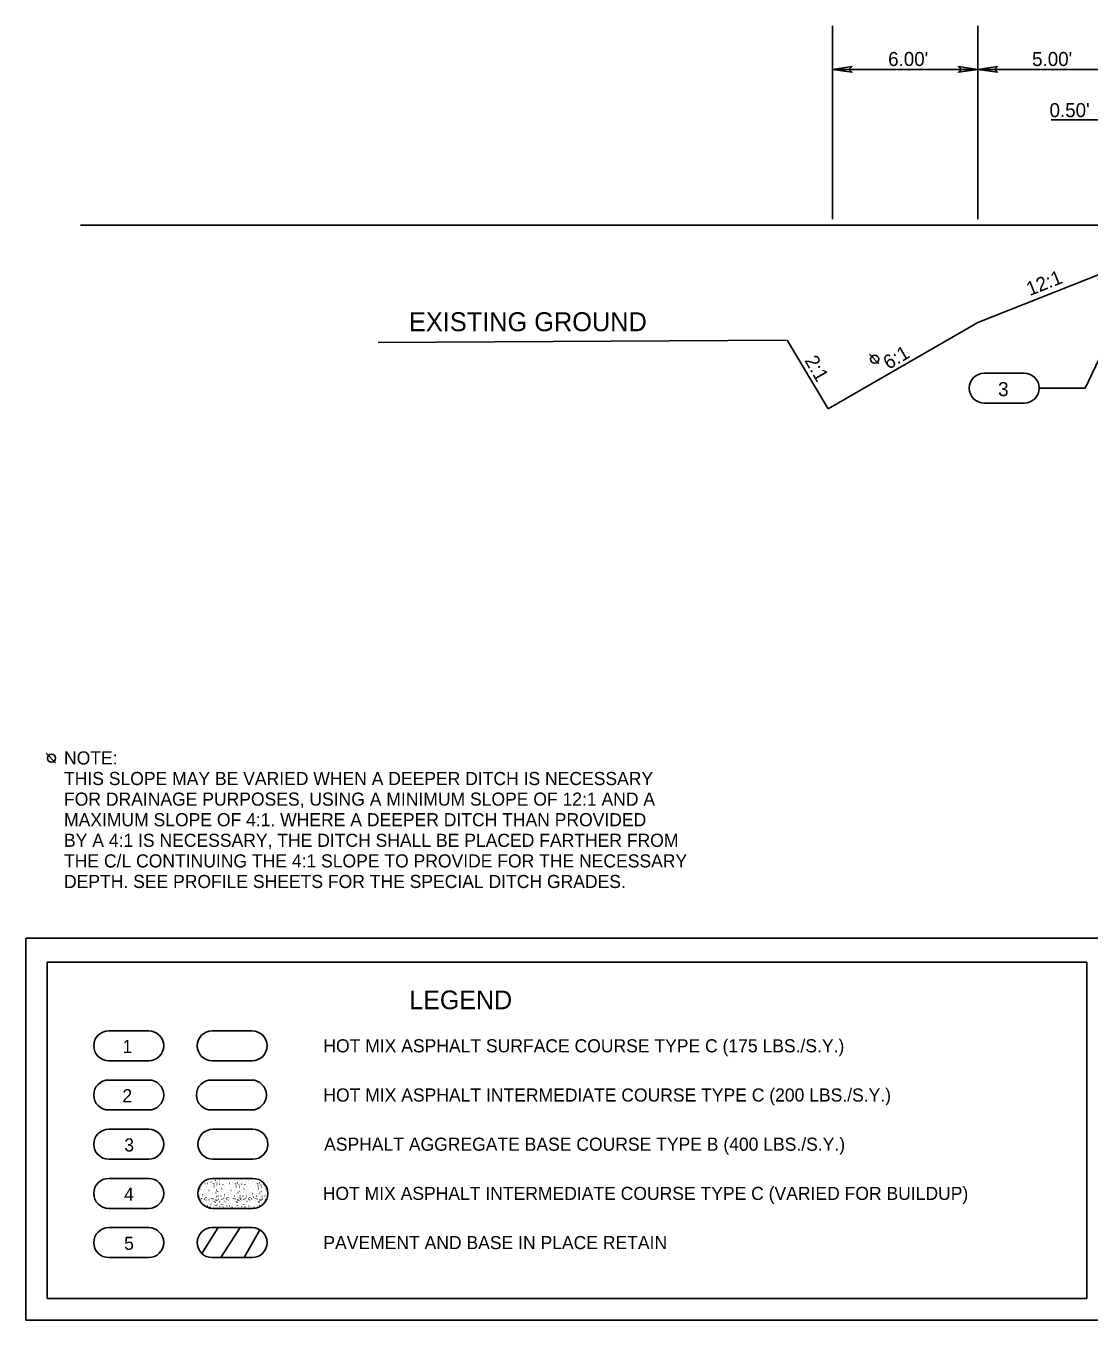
# Model space of a CAD drawing. Extents: x -8855 to -7217, y 44218 to 45252.
# Drawn here: x -8855 to -8287, y 44224 to 44916 of the extents above; entities that cross this region are included whole.
import ezdxf

# ---------------------------------------------------------------- set-up
doc = ezdxf.new("R2010")
doc.units = 0
for name, color, linetype in [('Default', 7, 'Continuous'), ('RD_EX_Misc', 7, 'Continuous'), ('RD_XS_Greenside', 7, 'Continuous'), ('RD_XS_Pave', 7, 'Continuous')]:
    doc.layers.add(name, color=color, linetype=linetype)

msp = doc.modelspace()

# ---------------------------------------------------------------- linework, layer by layer
at = {"layer": 'Default'}
for p, q in [((-8825.74, 44809.35), (-8001.4, 44809.35)), ((-8666.76, 44746.54), (-8448.82, 44747.86)), ((-8399.37, 44735.23), (-8404.39, 44740.39)), ((-8839.14, 44522.13), (-8844.16, 44527.29))]:
    msp.add_line(p, q, dxfattribs=at)
for points in [[(-8424.14, 44892.47), (-8413.75, 44893.97), (-8415.35, 44892.47), (-8413.75, 44890.98)], [(-8346.4, 44892.47), (-8356.79, 44890.98), (-8355.19, 44892.47), (-8356.79, 44893.97)], [(-8346.4, 44892.47), (-8336.01, 44893.97), (-8337.61, 44892.47), (-8336.01, 44890.98)]]:
    msp.add_lwpolyline(points, close=True, dxfattribs=at)
for centre in [(-8401.53, 44737.68), (-8841.3, 44524.59)]:
    msp.add_circle(centre, 2.17, dxfattribs=at)
at = {"layer": 'RD_EX_Misc'}
for p, q in [((-8424.14, 44812.42), (-8424.14, 44915.75)), ((-8346.4, 44812.42), (-8346.4, 44915.75)), ((-8346.4, 44892.47), (-8424.14, 44892.47)), ((-8346.4, 44892.47), (-8266.4, 44892.47)), ((-8307.35, 44865.58), (-8276.4, 44865.58)), ((-8289.09, 44722.23), (-8274.04, 44753.93)), ((-8321.67, 44730.23), (-8343.03, 44730.23)), ((-8313.67, 44722.23), (-8289.09, 44722.23)), ((-8343.03, 44714.23), (-8321.67, 44714.23)), ((-8810.73, 44378.93), (-8789.37, 44378.93)), ((-8734.11, 44378.93), (-8755.47, 44378.93)), ((-8789.37, 44362.93), (-8810.73, 44362.93)), ((-8755.47, 44362.93), (-8734.11, 44362.93)), ((-8810.73, 44352.65), (-8789.37, 44352.65)), ((-8789.37, 44336.65), (-8810.73, 44336.65)), ((-8810.73, 44326.37), (-8789.37, 44326.37)), ((-8755.07, 44326.37), (-8733.71, 44326.37)), ((-8755.07, 44326.37), (-8733.71, 44326.37)), ((-8789.37, 44310.37), (-8810.73, 44310.37)), ((-8733.71, 44310.37), (-8755.07, 44310.37)), ((-8733.71, 44310.37), (-8755.07, 44310.37)), ((-8810.73, 44300.09), (-8789.37, 44300.09)), ((-8761.66, 44296.07), (-8761.72, 44296.05)), ((-8761.42, 44296.74), (-8761.4, 44296.8)), ((-8760.61, 44295.64), (-8760.65, 44295.67)), ((-8759.3, 44297.31), (-8759.28, 44297.38)), ((-8758.29, 44299.27), (-8758.36, 44299.26)), ((-8758.28, 44295.94), (-8758.31, 44295.97)), ((-8757.84, 44297.37), (-8757.91, 44297.35)), ((-8757.4, 44298.63), (-8757.44, 44298.66)), ((-8756.69, 44294.89), (-8756.67, 44294.96)), ((-8756.54, 44296.77), (-8756.52, 44296.83)), ((-8756.08, 44298.15), (-8756.15, 44298.14)), ((-8755.66, 44299.31), (-8755.64, 44299.37)), ((-8755.6, 44295.58), (-8755.66, 44295.57)), ((-8754.79, 44297.4), (-8754.76, 44297.47)), ((-8754.49, 44296.57), (-8754.53, 44296.61)), ((-8754.39, 44295.5), (-8754.37, 44295.56)), ((-8754.27, 44299.64), (-8754.25, 44299.7)), ((-8753.75, 44299.12), (-8753.82, 44299.11)), ((-8753.69, 44297.7), (-8753.76, 44297.68)), ((-8753.72, 44296.23), (-8753.7, 44296.3)), ((-8752.92, 44296.57), (-8752.95, 44296.6)), ((-8752.9, 44297.73), (-8752.87, 44297.8)), ((-8752.63, 44295.46), (-8752.69, 44295.43)), ((-8752.57, 44298.72), (-8752.61, 44298.75)), ((-8751.65, 44299.49), (-8751.63, 44299.55)), ((-8751.42, 44296.97), (-8751.46, 44297)), ((-8751.39, 44298.54), (-8751.43, 44298.57)), ((-8751.15, 44295.73), (-8751.18, 44295.76)), ((-8750.47, 44298.22), (-8750.45, 44298.28)), ((-8749.92, 44296.07), (-8749.99, 44296.05)), ((-8749.69, 44296.74), (-8749.66, 44296.8)), ((-8749.23, 44300.03), (-8749.21, 44300.09)), ((-8749.18, 44297.87), (-8749.21, 44297.9)), ((-8748.88, 44295.64), (-8748.91, 44295.67)), ((-8748.58, 44299.78), (-8748.61, 44299.81)), ((-8747.76, 44298.78), (-8747.79, 44298.81)), ((-8747.57, 44297.31), (-8747.54, 44297.38)), ((-8746.56, 44299.27), (-8746.63, 44299.26)), ((-8746.55, 44295.94), (-8746.58, 44295.97)), ((-8746.11, 44297.37), (-8746.17, 44297.35)), ((-8745.67, 44298.63), (-8745.7, 44298.66)), ((-8744.96, 44294.89), (-8744.94, 44294.96)), ((-8744.81, 44296.77), (-8744.79, 44296.83)), ((-8744.35, 44298.15), (-8744.42, 44298.14)), ((-8743.93, 44299.31), (-8743.91, 44299.37)), ((-8743.86, 44295.58), (-8743.93, 44295.57)), ((-8743.05, 44297.4), (-8743.03, 44297.47)), ((-8742.76, 44296.57), (-8742.79, 44296.61)), ((-8742.66, 44295.5), (-8742.64, 44295.56)), ((-8742.54, 44299.64), (-8742.51, 44299.7)), ((-8742.02, 44299.12), (-8742.08, 44299.11)), ((-8741.96, 44297.7), (-8742.02, 44297.68)), ((-8741.99, 44296.23), (-8741.97, 44296.3)), ((-8741.19, 44296.57), (-8741.22, 44296.6)), ((-8741.16, 44297.73), (-8741.14, 44297.8)), ((-8740.89, 44295.46), (-8740.96, 44295.43)), ((-8740.84, 44298.72), (-8740.87, 44298.75)), ((-8739.92, 44299.49), (-8739.9, 44299.55)), ((-8739.69, 44296.97), (-8739.72, 44297)), ((-8739.66, 44298.54), (-8739.69, 44298.57)), ((-8739.42, 44295.73), (-8739.45, 44295.76)), ((-8738.74, 44298.22), (-8738.72, 44298.28)), ((-8738.19, 44296.07), (-8738.25, 44296.05)), ((-8737.95, 44296.74), (-8737.93, 44296.8)), ((-8737.5, 44300.03), (-8737.48, 44300.09)), ((-8737.45, 44297.87), (-8737.48, 44297.9)), ((-8737.14, 44295.64), (-8737.18, 44295.67)), ((-8736.84, 44299.78), (-8736.87, 44299.81)), ((-8736.02, 44298.78), (-8736.06, 44298.81)), ((-8735.83, 44297.31), (-8735.81, 44297.38)), ((-8734.83, 44299.27), (-8734.89, 44299.26)), ((-8734.81, 44295.94), (-8734.84, 44295.97)), ((-8734.37, 44297.37), (-8734.44, 44297.35)), ((-8733.93, 44298.63), (-8733.97, 44298.66)), ((-8733.23, 44294.89), (-8733.2, 44294.96)), ((-8733.07, 44296.77), (-8733.05, 44296.83)), ((-8732.61, 44298.15), (-8732.68, 44298.14)), ((-8732.2, 44299.31), (-8732.17, 44299.37)), ((-8732.13, 44295.58), (-8732.2, 44295.57)), ((-8731.32, 44297.4), (-8731.3, 44297.47)), ((-8731.03, 44296.57), (-8731.06, 44296.61)), ((-8730.92, 44295.5), (-8730.9, 44295.56)), ((-8730.28, 44299.12), (-8730.35, 44299.11)), ((-8730.22, 44297.7), (-8730.29, 44297.68)), ((-8730.26, 44296.23), (-8730.23, 44296.3)), ((-8729.45, 44296.57), (-8729.48, 44296.6)), ((-8729.43, 44297.73), (-8729.41, 44297.8)), ((-8729.16, 44295.46), (-8729.22, 44295.43)), ((-8727.95, 44296.97), (-8727.99, 44297)), ((-8727.68, 44295.73), (-8727.71, 44295.76)), ((-8762.57, 44290.66), (-8762.55, 44290.73)), ((-8762.21, 44289.23), (-8762.25, 44289.26)), ((-8762.19, 44292.95), (-8762.22, 44292.98)), ((-8762.09, 44288.91), (-8762.06, 44288.98)), ((-8762.03, 44294.41), (-8762, 44294.47)), ((-8761.11, 44289.45), (-8761.14, 44289.49)), ((-8760.9, 44293.62), (-8760.97, 44293.6)), ((-8760.97, 44288.06), (-8760.94, 44288.12)), ((-8760.69, 44291.26), (-8760.75, 44291.25)), ((-8760.44, 44290.39), (-8760.51, 44290.37)), ((-8760.42, 44292.05), (-8760.4, 44292.12)), ((-8760.31, 44287.8), (-8760.34, 44287.83)), ((-8759.72, 44288.61), (-8759.7, 44288.67)), ((-8759.51, 44294.17), (-8759.49, 44294.23)), ((-8759.41, 44289.16), (-8759.48, 44289.13)), ((-8758.76, 44289.97), (-8758.8, 44290.01)), ((-8758.75, 44288.54), (-8758.73, 44288.6)), ((-8758.33, 44292.75), (-8758.31, 44292.81)), ((-8758.23, 44291.2), (-8758.3, 44291.19)), ((-8757.98, 44289.23), (-8758.01, 44289.26)), ((-8757.48, 44292.05), (-8757.46, 44292.12)), ((-8757.14, 44288.59), (-8757.21, 44288.58)), ((-8757.13, 44293.55), (-8757.16, 44293.58)), ((-8756.74, 44290.1), (-8756.77, 44290.14)), ((-8755.8, 44288.31), (-8755.83, 44288.35)), ((-8755.79, 44289.21), (-8755.76, 44289.28)), ((-8755.48, 44293.62), (-8755.46, 44293.69)), ((-8755.39, 44291.81), (-8755.45, 44291.79)), ((-8755.18, 44290.6), (-8755.16, 44290.67)), ((-8754.88, 44289.03), (-8754.85, 44289.1)), ((-8754.73, 44289.66), (-8754.7, 44289.73)), ((-8754.27, 44287.66), (-8754.25, 44287.73)), ((-8754.24, 44291.96), (-8754.22, 44292.03)), ((-8754.07, 44294.46), (-8754.1, 44294.49)), ((-8753.98, 44291.07), (-8754.01, 44291.1)), ((-8753.84, 44292.95), (-8753.91, 44292.94)), ((-8753.66, 44290.01), (-8753.64, 44290.07)), ((-8753.48, 44292.24), (-8753.46, 44292.31)), ((-8753.42, 44288.73), (-8753.4, 44288.79)), ((-8753.3, 44288.19), (-8753.28, 44288.25)), ((-8753.25, 44289.36), (-8753.28, 44289.39)), ((-8753.05, 44293.9), (-8753.12, 44293.87)), ((-8753.05, 44290.36), (-8753.08, 44290.4)), ((-8752.93, 44288.18), (-8752.91, 44288.24)), ((-8752.66, 44292.99), (-8752.69, 44293.03)), ((-8752.43, 44294.29), (-8752.47, 44294.33)), ((-8752.3, 44289.68), (-8752.33, 44289.71)), ((-8752.25, 44290.72), (-8752.32, 44290.7)), ((-8752.29, 44291.87), (-8752.27, 44291.94)), ((-8752.17, 44288.85), (-8752.15, 44288.92)), ((-8751.78, 44289.1), (-8751.81, 44289.13)), ((-8751.15, 44288.4), (-8751.18, 44288.44)), ((-8750.84, 44290.66), (-8750.81, 44290.73)), ((-8750.48, 44289.23), (-8750.51, 44289.26)), ((-8750.45, 44292.95), (-8750.49, 44292.98)), ((-8750.35, 44288.91), (-8750.33, 44288.98)), ((-8750.29, 44294.41), (-8750.27, 44294.47)), ((-8749.37, 44289.45), (-8749.41, 44289.49)), ((-8749.16, 44293.62), (-8749.23, 44293.6)), ((-8749.23, 44288.06), (-8749.21, 44288.12)), ((-8748.95, 44291.26), (-8749.02, 44291.25)), ((-8748.71, 44290.39), (-8748.78, 44290.37)), ((-8748.69, 44292.05), (-8748.66, 44292.12)), ((-8748.58, 44287.8), (-8748.61, 44287.83)), ((-8747.99, 44288.61), (-8747.97, 44288.67)), ((-8747.78, 44294.17), (-8747.76, 44294.23)), ((-8747.68, 44289.16), (-8747.75, 44289.13)), ((-8747.03, 44289.97), (-8747.06, 44290.01)), ((-8747.02, 44288.54), (-8747, 44288.6)), ((-8746.6, 44292.75), (-8746.57, 44292.81)), ((-8746.5, 44291.2), (-8746.57, 44291.19)), ((-8746.25, 44289.23), (-8746.28, 44289.26)), ((-8745.75, 44292.05), (-8745.73, 44292.12)), ((-8745.41, 44288.59), (-8745.48, 44288.58)), ((-8745.4, 44293.55), (-8745.43, 44293.58)), ((-8745, 44290.1), (-8745.03, 44290.14)), ((-8744.06, 44288.31), (-8744.1, 44288.35)), ((-8744.05, 44289.21), (-8744.03, 44289.28)), ((-8743.75, 44293.62), (-8743.73, 44293.69)), ((-8743.65, 44291.81), (-8743.72, 44291.79)), ((-8743.45, 44290.6), (-8743.42, 44290.67)), ((-8743.14, 44289.03), (-8743.12, 44289.1)), ((-8742.99, 44289.66), (-8742.97, 44289.73)), ((-8742.54, 44287.66), (-8742.51, 44287.73)), ((-8742.51, 44291.96), (-8742.48, 44292.03)), ((-8742.34, 44294.46), (-8742.37, 44294.49)), ((-8742.25, 44291.07), (-8742.28, 44291.1)), ((-8742.11, 44292.95), (-8742.17, 44292.94)), ((-8741.93, 44290.01), (-8741.91, 44290.07)), ((-8741.75, 44292.24), (-8741.73, 44292.31)), ((-8741.69, 44288.73), (-8741.67, 44288.79)), ((-8741.57, 44288.19), (-8741.54, 44288.25)), ((-8741.51, 44289.36), (-8741.54, 44289.39)), ((-8741.32, 44293.9), (-8741.38, 44293.87)), ((-8741.32, 44290.36), (-8741.35, 44290.4)), ((-8741.19, 44288.18), (-8741.17, 44288.24)), ((-8740.93, 44292.99), (-8740.96, 44293.03)), ((-8740.7, 44294.29), (-8740.73, 44294.33)), ((-8740.57, 44289.68), (-8740.6, 44289.71)), ((-8740.52, 44290.72), (-8740.59, 44290.7)), ((-8740.56, 44291.87), (-8740.53, 44291.94)), ((-8740.43, 44288.85), (-8740.41, 44288.92)), ((-8740.05, 44289.1), (-8740.08, 44289.13)), ((-8739.42, 44288.4), (-8739.45, 44288.44)), ((-8739.1, 44290.66), (-8739.08, 44290.73)), ((-8738.75, 44289.23), (-8738.78, 44289.26)), ((-8738.72, 44292.95), (-8738.75, 44292.98)), ((-8738.62, 44288.91), (-8738.59, 44288.98)), ((-8738.56, 44294.41), (-8738.54, 44294.47)), ((-8737.64, 44289.45), (-8737.67, 44289.49)), ((-8737.43, 44293.62), (-8737.5, 44293.6)), ((-8737.5, 44288.06), (-8737.48, 44288.12)), ((-8737.22, 44291.26), (-8737.29, 44291.25)), ((-8736.98, 44290.39), (-8737.04, 44290.37)), ((-8736.95, 44292.05), (-8736.93, 44292.12)), ((-8736.84, 44287.8), (-8736.87, 44287.83)), ((-8736.25, 44288.61), (-8736.23, 44288.67)), ((-8736.04, 44294.17), (-8736.02, 44294.23)), ((-8735.95, 44289.16), (-8736.01, 44289.13)), ((-8735.29, 44289.97), (-8735.33, 44290.01)), ((-8735.29, 44288.54), (-8735.26, 44288.6)), ((-8734.86, 44292.75), (-8734.84, 44292.81)), ((-8734.76, 44291.2), (-8734.83, 44291.19)), ((-8734.51, 44289.23), (-8734.55, 44289.26)), ((-8734.01, 44292.05), (-8733.99, 44292.12)), ((-8733.67, 44288.59), (-8733.74, 44288.58)), ((-8733.66, 44293.55), (-8733.69, 44293.58)), ((-8733.27, 44290.1), (-8733.3, 44290.14)), ((-8732.33, 44288.31), (-8732.36, 44288.35)), ((-8732.32, 44289.21), (-8732.3, 44289.28)), ((-8732.01, 44293.62), (-8731.99, 44293.69)), ((-8731.92, 44291.81), (-8731.98, 44291.79)), ((-8731.71, 44290.6), (-8731.69, 44290.67)), ((-8731.41, 44289.03), (-8731.39, 44289.1)), ((-8731.26, 44289.66), (-8731.23, 44289.73)), ((-8730.8, 44287.66), (-8730.78, 44287.73)), ((-8730.77, 44291.96), (-8730.75, 44292.03)), ((-8730.6, 44294.46), (-8730.63, 44294.49)), ((-8730.51, 44291.07), (-8730.54, 44291.1)), ((-8730.37, 44292.95), (-8730.44, 44292.94)), ((-8730.2, 44290.01), (-8730.17, 44290.07)), ((-8730.01, 44292.24), (-8729.99, 44292.31)), ((-8729.95, 44288.73), (-8729.93, 44288.79)), ((-8729.83, 44288.19), (-8729.81, 44288.25)), ((-8729.78, 44289.36), (-8729.81, 44289.39)), ((-8729.58, 44293.9), (-8729.65, 44293.87)), ((-8729.58, 44290.36), (-8729.61, 44290.4)), ((-8729.46, 44288.18), (-8729.44, 44288.24)), ((-8729.19, 44292.99), (-8729.22, 44293.03)), ((-8728.96, 44294.29), (-8729, 44294.33)), ((-8728.83, 44289.68), (-8728.87, 44289.71)), ((-8728.79, 44290.72), (-8728.85, 44290.7)), ((-8728.82, 44291.87), (-8728.8, 44291.94)), ((-8728.7, 44288.85), (-8728.68, 44288.92)), ((-8728.31, 44289.1), (-8728.35, 44289.13)), ((-8727.68, 44288.4), (-8727.71, 44288.44)), ((-8727.37, 44290.66), (-8727.35, 44290.73)), ((-8727.01, 44289.23), (-8727.04, 44289.26)), ((-8726.99, 44292.95), (-8727.02, 44292.98)), ((-8726.88, 44288.91), (-8726.86, 44288.98)), ((-8726.82, 44294.41), (-8726.8, 44294.47)), ((-8789.37, 44284.09), (-8810.73, 44284.09)), ((-8759.49, 44286.8), (-8759.53, 44286.84)), ((-8759.29, 44285.38), (-8759.28, 44285.4)), ((-8758.29, 44287.29), (-8758.36, 44287.28)), ((-8757.84, 44285.39), (-8757.91, 44285.38)), ((-8757.4, 44286.65), (-8757.44, 44286.68)), ((-8756.54, 44284.79), (-8756.52, 44284.86)), ((-8756.08, 44286.18), (-8756.15, 44286.16)), ((-8755.66, 44287.33), (-8755.64, 44287.39)), ((-8754.79, 44285.43), (-8754.76, 44285.49)), ((-8754.49, 44284.6), (-8754.53, 44284.63)), ((-8753.75, 44287.14), (-8753.82, 44287.13)), ((-8753.69, 44285.72), (-8753.76, 44285.71)), ((-8753.72, 44284.26), (-8753.7, 44284.32)), ((-8752.92, 44284.59), (-8752.95, 44284.62)), ((-8752.9, 44285.76), (-8752.87, 44285.82)), ((-8752.57, 44286.74), (-8752.61, 44286.78)), ((-8751.65, 44287.51), (-8751.63, 44287.58)), ((-8751.42, 44284.99), (-8751.46, 44285.02)), ((-8751.39, 44286.56), (-8751.43, 44286.59)), ((-8750.47, 44286.24), (-8750.45, 44286.31)), ((-8749.69, 44284.76), (-8749.66, 44284.83)), ((-8749.18, 44285.9), (-8749.21, 44285.93)), ((-8747.76, 44286.8), (-8747.79, 44286.84)), ((-8747.57, 44285.34), (-8747.54, 44285.4)), ((-8746.56, 44287.29), (-8746.63, 44287.28)), ((-8746.11, 44285.39), (-8746.17, 44285.38)), ((-8745.67, 44286.65), (-8745.7, 44286.68)), ((-8744.81, 44284.79), (-8744.79, 44284.86)), ((-8744.35, 44286.18), (-8744.42, 44286.16)), ((-8743.93, 44287.33), (-8743.91, 44287.39)), ((-8743.05, 44285.43), (-8743.03, 44285.49)), ((-8742.76, 44284.6), (-8742.79, 44284.63)), ((-8742.02, 44287.14), (-8742.08, 44287.13)), ((-8741.96, 44285.72), (-8742.02, 44285.71)), ((-8741.99, 44284.26), (-8741.97, 44284.32)), ((-8741.19, 44284.59), (-8741.22, 44284.62)), ((-8741.16, 44285.76), (-8741.14, 44285.82)), ((-8740.84, 44286.74), (-8740.87, 44286.78)), ((-8739.92, 44287.51), (-8739.9, 44287.58)), ((-8739.69, 44284.99), (-8739.72, 44285.02)), ((-8739.66, 44286.56), (-8739.69, 44286.59)), ((-8738.74, 44286.24), (-8738.72, 44286.31)), ((-8737.95, 44284.76), (-8737.93, 44284.83)), ((-8737.45, 44285.9), (-8737.48, 44285.93)), ((-8736.02, 44286.8), (-8736.06, 44286.84)), ((-8735.83, 44285.34), (-8735.81, 44285.4)), ((-8734.83, 44287.29), (-8734.89, 44287.28)), ((-8734.37, 44285.39), (-8734.44, 44285.38)), ((-8733.93, 44286.65), (-8733.97, 44286.68)), ((-8733.07, 44284.79), (-8733.05, 44284.86)), ((-8732.61, 44286.18), (-8732.68, 44286.16)), ((-8732.2, 44287.33), (-8732.17, 44287.39)), ((-8731.32, 44285.43), (-8731.3, 44285.49)), ((-8730.28, 44287.14), (-8730.35, 44287.13)), ((-8730.22, 44285.72), (-8730.29, 44285.71)), ((-8729.43, 44285.76), (-8729.41, 44285.82)), ((-8729.11, 44286.74), (-8729.14, 44286.78)), ((-8728.19, 44287.51), (-8728.16, 44287.58)), ((-8810.73, 44273.81), (-8789.37, 44273.81)), ((-8789.37, 44257.81), (-8810.73, 44257.81))]:
    msp.add_line(p, q, dxfattribs=at)
for points in [[(-8854.98, 44428.43), (-8275.6, 44428.43), (-8275.6, 44224.4), (-8854.98, 44224.4)], [(-8843.52, 44415.54), (-8288.3, 44415.54), (-8288.3, 44235.99), (-8843.52, 44235.99)]]:
    msp.add_lwpolyline(points, close=True, dxfattribs=at)
for points in [[(-8734.51, 44352.65), (-8755.87, 44352.65)], [(-8755.87, 44336.65), (-8734.51, 44336.65)]]:
    msp.add_lwpolyline(points, dxfattribs=at)
for centre, start, end in [((-8343.03, 44722.23), 90.00003, 270.00003), ((-8321.67, 44722.23), 270, 90), ((-8810.73, 44370.93), 90, 270), ((-8789.37, 44370.93), 269.99997, 89.99997), ((-8755.47, 44370.93), 90, 270), ((-8734.11, 44370.93), 269.99997, 89.99997), ((-8810.73, 44344.65), 90, 270), ((-8789.37, 44344.65), 269.99997, 89.99997), ((-8755.87, 44344.65), 90, 270), ((-8734.51, 44344.65), 269.99997, 89.99997), ((-8810.73, 44318.37), 90, 270), ((-8789.37, 44318.37), 269.99997, 89.99997), ((-8755.07, 44318.37), 90, 270), ((-8755.07, 44318.37), 90, 270), ((-8733.71, 44318.37), 269.99997, 89.99997), ((-8733.71, 44318.37), 269.99997, 89.99997), ((-8810.73, 44292.09), 90, 270), ((-8789.37, 44292.09), 269.99997, 89.99997), ((-8810.73, 44265.81), 90, 270), ((-8789.37, 44265.81), 269.99997, 89.99997)]:
    msp.add_arc(centre, 8, start, end, dxfattribs=at)
at = {"layer": 'RD_XS_Greenside'}
for p, q in [((-8266.4, 44789), (-8346.4, 44757.25)), ((-8346.4, 44757.25), (-8426.4, 44711.19)), ((-8448.34, 44747.87), (-8426.4, 44711.19))]:
    msp.add_line(p, q, dxfattribs=at)
at = {"layer": 'RD_XS_Pave'}
for p, q in [((-8755.07, 44300.09), (-8733.71, 44300.09)), ((-8733.71, 44284.09), (-8755.07, 44284.09)), ((-8752.21, 44273.81), (-8761, 44260.04)), ((-8755.47, 44273.81), (-8734.11, 44273.81)), ((-8740.42, 44273.81), (-8750.79, 44257.81)), ((-8729.96, 44272.65), (-8738.39, 44257.81)), ((-8734.11, 44257.81), (-8755.47, 44257.81))]:
    msp.add_line(p, q, dxfattribs=at)
for centre, start, end in [((-8755.07, 44292.09), 90, 270), ((-8733.71, 44292.09), 269.99997, 89.99997), ((-8755.47, 44265.81), 90, 270), ((-8734.11, 44265.81), 269.99997, 89.99997)]:
    msp.add_arc(centre, 8, start, end, dxfattribs=at)

# ---------------------------------------------------------------- texts
at = {"layer": 'Default'}
for s, p in [('NOTE:', (-8834.6, 44521.21)), ('THIS SLOPE MAY BE VARIED WHEN A DEEPER DITCH IS NECESSARY', (-8834.6, 44510.21)), ('FOR DRAINAGE PURPOSES, USING A MINIMUM SLOPE OF 12:1 AND A', (-8834.6, 44499.21)), ('MAXIMUM SLOPE OF 4:1. WHERE A DEEPER DITCH THAN PROVIDED', (-8834.6, 44488.21)), ('BY A 4:1 IS NECESSARY, THE DITCH SHALL BE PLACED FARTHER FROM', (-8834.6, 44477.21)), ('THE C/L CONTINUING THE 4:1 SLOPE TO PROVIDE FOR THE NECESSARY', (-8834.6, 44466.21)), ('DEPTH. SEE PROFILE SHEETS FOR THE SPECIAL DITCH GRADES.', (-8834.6, 44455.21))]:
    msp.add_text(s, height=7, dxfattribs=at).set_placement(p)
at = {"layer": 'RD_EX_Misc'}
for s, height, p in [("6.00'", 7.5, (-8394.37, 44894.31)), ("5.00'", 7.5, (-8317.46, 44894.31)), ("0.50'", 7.5, (-8308.14, 44867.01)), ('EXISTING GROUND ', 10.1189, (-8650.32, 44752.65)), ('3', 7.5, (-8335.62, 44717.96)), ('LEGEND', 10, (-8650.19, 44390.47)), ('1', 7, (-8803.36, 44367.04)), ('HOT MIX ASPHALT SURFACE COURSE TYPE C (175 LBS./S.Y.)', 7, (-8696.06, 44367.43)), ('2', 7, (-8803.42, 44340.76)), ('HOT MIX ASPHALT INTERMEDIATE COURSE TYPE C (200 LBS./S.Y.)', 7, (-8696.06, 44341.15)), ('3', 7, (-8802.39, 44314.48)), ('ASPHALT AGGREGATE BASE COURSE TYPE B (400 LBS./S.Y.)', 7, (-8695.66, 44314.87)), ('4', 7, (-8802.52, 44288.2)), ('HOT MIX ASPHALT INTERMEDIATE COURSE TYPE C (VARIED FOR BUILDUP)', 7, (-8696.38, 44288.59)), ('5', 7, (-8802.49, 44261.93)), ('PAVEMENT AND BASE IN PLACE RETAIN', 7, (-8696.06, 44262.31))]:
    msp.add_text(s, height=height, dxfattribs=at).set_placement(p)
for s, rotation, p in [('12:1', 21.64467, (-8318.72, 44771.39)), ('6:1', 30.39484, (-8394.19, 44731.94)), ('2:1', 299.83416, (-8439.2, 44737.04))]:
    msp.add_text(s, height=7.5, rotation=rotation, dxfattribs=at).set_placement(p)

doc.saveas('drawing.dxf')
